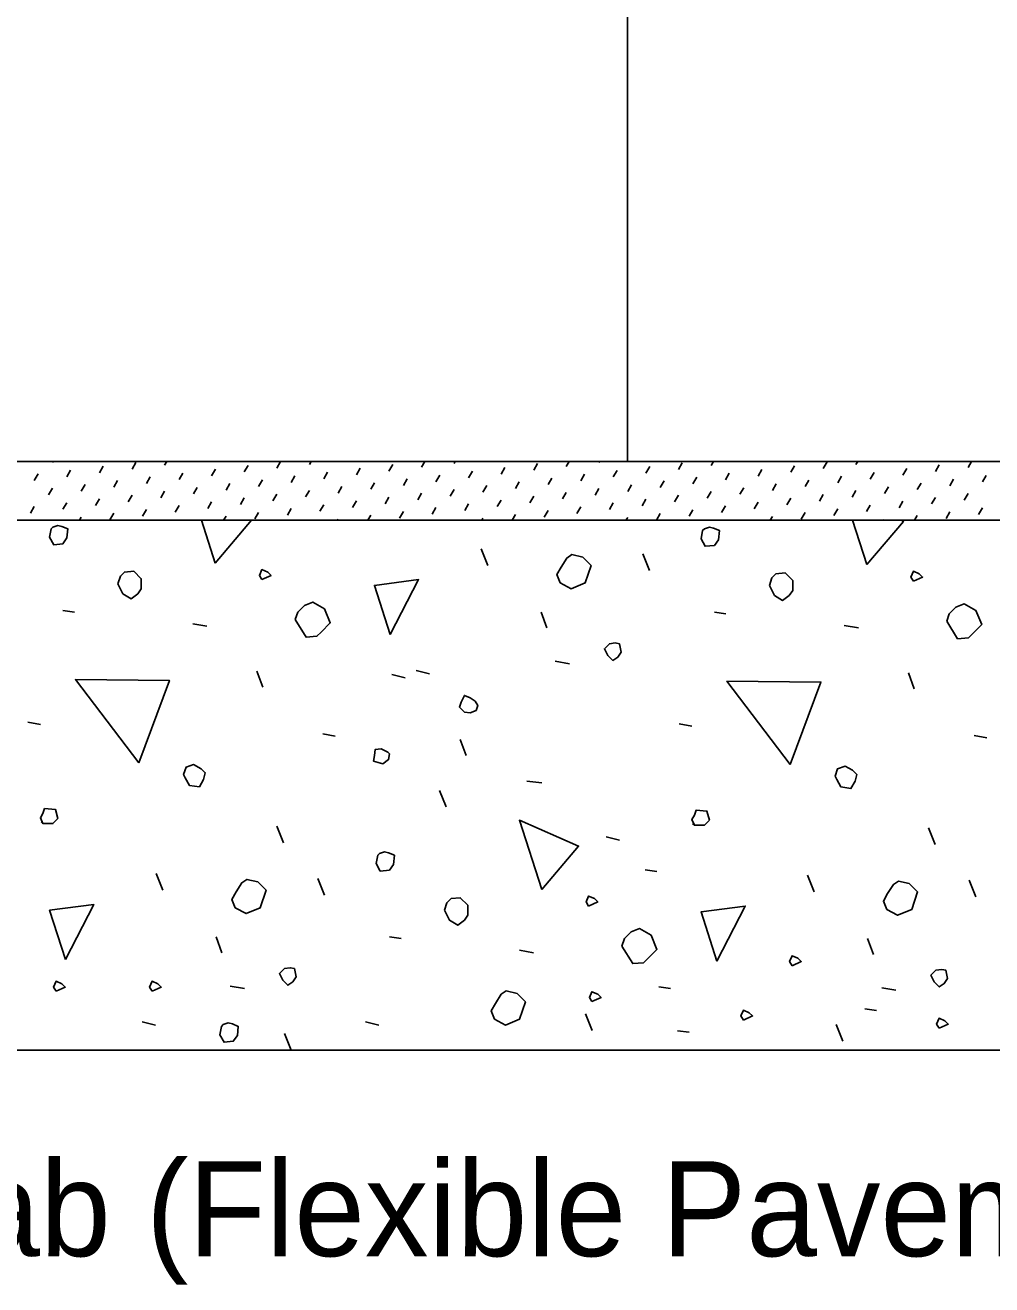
# Model space of a CAD drawing. Extents: x 0.5 to 40.8, y 1 to 25.8.
# Drawn here: x 4.34 to 6.391, y 9.937 to 12.611 of the extents above; entities that cross this region are included whole.
import ezdxf

# ---------------------------------------------------------------- set-up
doc = ezdxf.new("R2010")
doc.units = 0
for name, color, linetype in [('Dimension', 7, 'Continuous'), ('Miscellaneous', 7, 'Continuous'), ('TrafBarrierConc', 7, 'Continuous')]:
    doc.layers.add(name, color=color, linetype=linetype)

msp = doc.modelspace()

# ---------------------------------------------------------------- linework, layer by layer
at = {"layer": 'Miscellaneous'}
for p, q in [((4.3978, 11.6829), (4.3989, 11.6848)), ((4.4283, 11.6524), (4.4364, 11.6664)), ((4.4975, 11.6605), (4.5056, 11.6745)), ((4.5667, 11.6686), (4.5748, 11.6826)), ((4.6358, 11.6767), (4.6405, 11.6848)), ((4.6664, 11.6462), (4.6745, 11.6602)), ((4.7355, 11.6543), (4.7436, 11.6683)), ((4.8047, 11.6624), (4.8128, 11.6764)), ((4.8739, 11.6705), (4.882, 11.6845)), ((4.943, 11.6786), (4.9466, 11.6848)), ((4.9735, 11.6481), (4.9816, 11.6621)), ((5.0427, 11.6562), (5.0508, 11.6702)), ((5.1119, 11.6643), (5.12, 11.6783)), ((5.181, 11.6724), (5.1882, 11.6848)), ((5.2502, 11.6805), (5.2527, 11.6848)), ((5.2807, 11.6499), (5.2888, 11.6639)), ((5.3499, 11.658), (5.358, 11.672)), ((5.4191, 11.6661), (5.4272, 11.6801)), ((5.4882, 11.6742), (5.4943, 11.6848)), ((5.5574, 11.6823), (5.5588, 11.6848)), ((5.5879, 11.6518), (5.596, 11.6658)), ((5.6571, 11.6599), (5.6652, 11.6739)), ((5.7262, 11.668), (5.7343, 11.682)), ((5.7954, 11.6761), (5.8004, 11.6848)), ((5.8259, 11.6456), (5.834, 11.6596)), ((5.8646, 11.6842), (5.8649, 11.6848)), ((5.8951, 11.6537), (5.9032, 11.6677)), ((5.9643, 11.6618), (5.9724, 11.6758)), ((6.0334, 11.6699), (6.0415, 11.6839)), ((6.1026, 11.678), (6.1065, 11.6848)), ((6.1331, 11.6475), (6.1412, 11.6615)), ((6.2023, 11.6556), (6.2104, 11.6696)), ((6.2715, 11.6637), (6.2796, 11.6777)), ((6.3406, 11.6718), (6.3482, 11.6848)), ((4.3592, 11.6443), (4.3673, 11.6583)), ((4.4589, 11.6219), (4.467, 11.6359)), ((4.528, 11.63), (4.5361, 11.644)), ((4.5972, 11.6381), (4.6053, 11.6521)), ((4.7661, 11.6238), (4.7742, 11.6378)), ((4.8352, 11.6319), (4.8433, 11.6459)), ((4.9044, 11.64), (4.9125, 11.654)), ((5.0732, 11.6256), (5.0813, 11.6396)), ((5.1424, 11.6337), (5.1505, 11.6477)), ((5.2116, 11.6418), (5.2197, 11.6558)), ((5.3113, 11.6194), (5.3194, 11.6334)), ((5.3804, 11.6275), (5.3885, 11.6415)), ((5.4496, 11.6356), (5.4577, 11.6496)), ((5.5188, 11.6437), (5.5269, 11.6577)), ((5.6184, 11.6213), (5.6266, 11.6353)), ((5.6876, 11.6294), (5.6957, 11.6434)), ((5.7568, 11.6375), (5.7649, 11.6515)), ((5.9256, 11.6232), (5.9337, 11.6372)), ((5.9948, 11.6313), (6.0029, 11.6453)), ((6.064, 11.6394), (6.0721, 11.6534)), ((6.2328, 11.625), (6.2409, 11.639)), ((6.302, 11.6331), (6.3101, 11.6471)), ((6.3711, 11.6412), (6.3793, 11.6552)), ((4.3897, 11.6138), (4.3978, 11.6278)), ((4.4894, 11.5913), (4.4975, 11.6053)), ((4.5586, 11.5994), (4.5667, 11.6134)), ((4.6277, 11.6076), (4.6358, 11.6215)), ((4.6969, 11.6157), (4.705, 11.6296)), ((4.7966, 11.5932), (4.8047, 11.6072)), ((4.8657, 11.6013), (4.8739, 11.6153)), ((4.9349, 11.6094), (4.943, 11.6234)), ((5.0041, 11.6175), (5.0122, 11.6315)), ((5.1038, 11.5951), (5.1119, 11.6091)), ((5.1729, 11.6032), (5.181, 11.6172)), ((5.2421, 11.6113), (5.2502, 11.6253)), ((5.411, 11.597), (5.4191, 11.611)), ((5.4801, 11.6051), (5.4882, 11.6191)), ((5.5493, 11.6132), (5.5574, 11.6272)), ((5.7181, 11.5989), (5.7262, 11.6129)), ((5.7873, 11.607), (5.7954, 11.621)), ((5.8565, 11.6151), (5.8646, 11.6291)), ((5.9562, 11.5926), (5.9643, 11.6066)), ((6.0253, 11.6007), (6.0334, 11.6147)), ((6.0945, 11.6088), (6.1026, 11.6228)), ((6.1637, 11.6169), (6.1718, 11.6309)), ((6.2634, 11.5945), (6.2715, 11.6085)), ((6.3325, 11.6026), (6.3406, 11.6166)), ((4.3511, 11.5751), (4.3592, 11.5891)), ((4.4202, 11.5832), (4.4283, 11.5972)), ((4.5891, 11.5689), (4.5972, 11.5829)), ((4.6583, 11.577), (4.6664, 11.591)), ((4.7274, 11.5851), (4.7355, 11.5991)), ((4.8963, 11.5708), (4.9044, 11.5848)), ((4.9654, 11.5789), (4.9735, 11.5929)), ((5.0346, 11.587), (5.0427, 11.601)), ((5.1343, 11.5646), (5.1424, 11.5786)), ((5.2035, 11.5727), (5.2116, 11.5867)), ((5.2726, 11.5808), (5.2807, 11.5948)), ((5.3418, 11.5889), (5.3499, 11.6029)), ((5.4415, 11.5665), (5.4496, 11.5804)), ((5.5107, 11.5746), (5.5188, 11.5885)), ((5.5798, 11.5827), (5.5879, 11.5966)), ((5.649, 11.5908), (5.6571, 11.6048)), ((5.7487, 11.5683), (5.7568, 11.5823)), ((5.8178, 11.5764), (5.8259, 11.5904)), ((5.887, 11.5845), (5.8951, 11.5985)), ((6.0559, 11.5702), (6.064, 11.5842)), ((6.125, 11.5783), (6.1331, 11.5923)), ((6.1942, 11.5864), (6.2023, 11.6004)), ((6.363, 11.5721), (6.3711, 11.5861)), ((4.4549, 11.5598), (4.4589, 11.5667)), ((4.5199, 11.5608), (4.528, 11.5748)), ((4.6965, 11.5598), (4.6969, 11.5605)), ((4.761, 11.5598), (4.7661, 11.5686)), ((4.8271, 11.5627), (4.8352, 11.5767)), ((5.0026, 11.5598), (5.0041, 11.5624)), ((5.0671, 11.5598), (5.0732, 11.5705)), ((5.3087, 11.5598), (5.3113, 11.5642)), ((5.3732, 11.5598), (5.3804, 11.5723)), ((5.6148, 11.5598), (5.6184, 11.5661)), ((5.6795, 11.5602), (5.6876, 11.5742)), ((5.8564, 11.5598), (5.8565, 11.5599)), ((5.9209, 11.5598), (5.9256, 11.568)), ((5.9867, 11.5621), (5.9948, 11.5761)), ((6.1625, 11.5598), (6.1637, 11.5618)), ((6.227, 11.5598), (6.2328, 11.5699)), ((6.2939, 11.564), (6.302, 11.578)), ((5.3215, 11.4639), (5.3073, 11.4993)), ((5.6644, 11.4533), (5.6503, 11.4887)), ((4.4199, 11.3685), (4.4446, 11.3649)), ((5.447, 11.3313), (5.4346, 11.3649)), ((5.8023, 11.3649), (5.827, 11.3614)), ((4.6957, 11.3402), (4.7257, 11.3349)), ((6.0781, 11.3366), (6.1081, 11.3313)), ((5.4646, 11.2606), (5.4947, 11.2553)), ((4.8442, 11.2058), (4.8318, 11.2394)), ((5.1182, 11.2324), (5.1465, 11.2253)), ((5.1694, 11.2412), (5.1977, 11.2341)), ((6.2266, 11.2023), (6.2142, 11.2359)), ((4.3457, 11.1316), (4.3722, 11.1263)), ((5.728, 11.1281), (5.7546, 11.1227)), ((4.9714, 11.1068), (4.998, 11.1015)), ((6.3538, 11.1033), (6.3804, 11.098)), ((5.2755, 11.0609), (5.2631, 11.0945)), ((5.4045, 11.0061), (5.4364, 11.0025)), ((5.2331, 10.9513), (5.2189, 10.9866)), ((4.8884, 10.8753), (4.8742, 10.9106)), ((5.5725, 10.8876), (5.6008, 10.8806)), ((6.2707, 10.8717), (6.2566, 10.9071)), ((4.632, 10.7745), (4.6179, 10.8099)), ((5.6553, 10.8177), (5.68, 10.8142)), ((6.0144, 10.771), (6.0003, 10.8063)), ((4.975, 10.7639), (4.9608, 10.7992)), ((6.3574, 10.7604), (6.3432, 10.7957)), ((4.7575, 10.6419), (4.7452, 10.6755)), ((5.1129, 10.6755), (5.1376, 10.672)), ((6.1399, 10.6384), (6.1276, 10.672)), ((5.3886, 10.6472), (5.4187, 10.6419)), ((4.7752, 10.5712), (4.8053, 10.5659)), ((5.6847, 10.5697), (5.7095, 10.5662)), ((6.1576, 10.5677), (6.1877, 10.5624)), ((5.5429, 10.4768), (5.5288, 10.5122)), ((6.1218, 10.523), (6.1466, 10.5195)), ((4.5883, 10.4953), (4.6166, 10.4883)), ((5.0622, 10.4953), (5.0905, 10.4883)), ((6.0749, 10.4543), (6.0608, 10.4896)), ((4.9045, 10.4351), (4.8903, 10.4705)), ((5.724, 10.4764), (5.7488, 10.4729))]:
    msp.add_line(p, q, dxfattribs=at)
for points in [[(4.7434, 11.4692), (4.7139, 11.5598)], [(4.82, 11.5598), (4.7434, 11.4692)], [(6.1258, 11.4657), (6.0952, 11.5598)], [(6.1986, 11.5598), (6.2036, 11.5576), (6.1258, 11.4657)], [(4.3916, 11.524), (4.4005, 11.5081), (4.4199, 11.5099), (4.4287, 11.5223), (4.4305, 11.5417), (4.4181, 11.547), (4.4093, 11.5488), (4.3987, 11.5452), (4.3951, 11.5417), (4.3916, 11.524)], [(5.774, 11.5205), (5.7828, 11.5046), (5.8023, 11.5064), (5.8111, 11.5187), (5.8129, 11.5382), (5.8005, 11.5435), (5.7917, 11.5452), (5.7811, 11.5417), (5.7775, 11.5382), (5.774, 11.5205)], [(5.4753, 11.4268), (5.4982, 11.4144), (5.5283, 11.4268), (5.5407, 11.4639), (5.523, 11.4816), (5.5, 11.4869), (5.4894, 11.4798), (5.477, 11.4604), (5.4682, 11.4445), (5.4753, 11.4268)], [(4.5366, 11.425), (4.5472, 11.4038), (4.5649, 11.3932), (4.579, 11.4038), (4.5861, 11.4144), (4.5861, 11.4356), (4.5702, 11.4516), (4.5507, 11.4498), (4.5419, 11.4409), (4.5366, 11.425)], [(4.8424, 11.4339), (4.8618, 11.4427), (4.8548, 11.4498), (4.8424, 11.4551), (4.8371, 11.4427), (4.8424, 11.4339)], [(5.919, 11.4215), (5.9296, 11.4003), (5.9472, 11.3897), (5.9614, 11.4003), (5.9685, 11.4109), (5.9685, 11.4321), (5.9526, 11.448), (5.9331, 11.4463), (5.9243, 11.4374), (5.919, 11.4215)], [(6.2248, 11.4303), (6.2442, 11.4392), (6.2372, 11.4463), (6.2248, 11.4516), (6.2195, 11.4392), (6.2248, 11.4303)], [(5.1146, 11.3172), (5.081, 11.4215), (5.1747, 11.4339), (5.1146, 11.3172)], [(4.9131, 11.349), (4.9361, 11.3119), (4.9591, 11.3137), (4.9679, 11.3225), (4.9874, 11.342), (4.975, 11.372), (4.9502, 11.3861), (4.9326, 11.3791), (4.9184, 11.3649), (4.9131, 11.349)], [(6.2955, 11.3455), (6.3185, 11.3084), (6.3415, 11.3101), (6.3503, 11.319), (6.3697, 11.3384), (6.3574, 11.3685), (6.3326, 11.3826), (6.3149, 11.3755), (6.3008, 11.3614), (6.2955, 11.3455)], [(5.576, 11.273), (5.5866, 11.2624), (5.5972, 11.2695), (5.6043, 11.2801), (5.6008, 11.2978), (5.5919, 11.2995), (5.5796, 11.2978), (5.5689, 11.2872), (5.576, 11.273)], [(4.5808, 11.045), (4.4464, 11.2217), (4.6462, 11.22), (4.5808, 11.045)], [(5.9632, 11.0414), (5.8288, 11.2182), (6.0286, 11.2164), (5.9632, 11.0414)], [(5.272, 11.1528), (5.2843, 11.151), (5.2967, 11.1563), (5.3002, 11.1669), (5.2949, 11.1758), (5.2843, 11.1829), (5.272, 11.1882), (5.2649, 11.174), (5.2614, 11.1634), (5.272, 11.1528)], [(5.0793, 11.0485), (5.0987, 11.0432), (5.1111, 11.052), (5.1129, 11.0644), (5.1093, 11.0679), (5.0952, 11.075), (5.0828, 11.0733), (5.081, 11.0609), (5.0793, 11.0485)], [(4.6798, 11.0131), (4.6886, 10.9972), (4.7098, 10.9937), (4.7187, 11.0096), (4.7222, 11.0238), (4.7133, 11.0326), (4.6974, 11.0414), (4.6815, 11.0361), (4.6762, 11.0202), (4.6798, 11.0131)], [(6.0622, 11.0096), (6.071, 10.9937), (6.0922, 10.9902), (6.101, 11.0061), (6.1046, 11.0202), (6.0957, 11.0291), (6.0798, 11.0379), (6.0639, 11.0326), (6.0586, 11.0167), (6.0622, 11.0096)], [(4.3775, 10.9159), (4.3987, 10.9159), (4.4093, 10.9265), (4.404, 10.946), (4.381, 10.9477), (4.3775, 10.9371), (4.3722, 10.9283), (4.3775, 10.9159), (4.3739, 10.9195)], [(5.7599, 10.9124), (5.7811, 10.9124), (5.7917, 10.923), (5.7864, 10.9424), (5.7634, 10.9442), (5.7599, 10.9336), (5.7546, 10.9248), (5.7599, 10.9124), (5.7563, 10.9159)], [(5.4364, 10.7763), (5.3886, 10.923), (5.5141, 10.8682), (5.4364, 10.7763)], [(5.0846, 10.8311), (5.0934, 10.8152), (5.1129, 10.8169), (5.1217, 10.8293), (5.1235, 10.8487), (5.1111, 10.854), (5.1023, 10.8558), (5.0916, 10.8523), (5.0881, 10.8487), (5.0846, 10.8311)], [(4.7858, 10.7374), (4.8088, 10.725), (4.8389, 10.7374), (4.8512, 10.7745), (4.8336, 10.7922), (4.8106, 10.7975), (4.8, 10.7904), (4.7876, 10.771), (4.7788, 10.7551), (4.7858, 10.7374)], [(6.1682, 10.7338), (6.1912, 10.7215), (6.2213, 10.7338), (6.2336, 10.771), (6.2159, 10.7886), (6.193, 10.7939), (6.1824, 10.7869), (6.17, 10.7674), (6.1611, 10.7515), (6.1682, 10.7338)], [(5.2295, 10.7321), (5.2401, 10.7109), (5.2578, 10.7003), (5.272, 10.7109), (5.279, 10.7215), (5.279, 10.7427), (5.2631, 10.7586), (5.2437, 10.7568), (5.2348, 10.748), (5.2295, 10.7321)], [(5.5354, 10.7409), (5.5548, 10.7498), (5.5477, 10.7568), (5.5354, 10.7621), (5.5301, 10.7498), (5.5354, 10.7409)], [(4.4252, 10.6278), (4.3916, 10.7321), (4.4853, 10.7444), (4.4252, 10.6278)], [(5.8076, 10.6242), (5.774, 10.7285), (5.8677, 10.7409), (5.8076, 10.6242)], [(5.6061, 10.6561), (5.6291, 10.6189), (5.652, 10.6207), (5.6609, 10.6295), (5.6803, 10.649), (5.6679, 10.679), (5.6432, 10.6932), (5.6255, 10.6861), (5.6114, 10.672), (5.6061, 10.6561)], [(5.9672, 10.6141), (5.9867, 10.623), (5.9796, 10.63), (5.9672, 10.6353), (5.9619, 10.623), (5.9672, 10.6141)], [(4.8866, 10.5836), (4.8972, 10.573), (4.9078, 10.58), (4.9149, 10.5907), (4.9113, 10.6083), (4.9025, 10.6101), (4.8901, 10.6083), (4.8795, 10.5977), (4.8866, 10.5836)], [(6.269, 10.58), (6.2796, 10.5694), (6.2902, 10.5765), (6.2973, 10.5871), (6.2937, 10.6048), (6.2849, 10.6066), (6.2725, 10.6048), (6.2619, 10.5942), (6.269, 10.58)], [(4.4056, 10.5601), (4.425, 10.5689), (4.4179, 10.576), (4.4056, 10.5813), (4.4003, 10.5689), (4.4056, 10.5601)], [(4.6094, 10.5601), (4.6288, 10.5689), (4.6217, 10.576), (4.6094, 10.5813), (4.6041, 10.5689), (4.6094, 10.5601)], [(5.336, 10.5007), (5.359, 10.4884), (5.389, 10.5007), (5.4014, 10.5379), (5.3837, 10.5555), (5.3607, 10.5608), (5.3501, 10.5538), (5.3378, 10.5343), (5.3289, 10.5184), (5.336, 10.5007)], [(5.5424, 10.538), (5.5619, 10.5468), (5.5548, 10.5539), (5.5424, 10.5592), (5.5371, 10.5468), (5.5424, 10.538)], [(5.8641, 10.4987), (5.8835, 10.5076), (5.8765, 10.5146), (5.8641, 10.5199), (5.8588, 10.5076), (5.8641, 10.4987)], [(4.7531, 10.4679), (4.7619, 10.452), (4.7814, 10.4538), (4.7902, 10.4662), (4.792, 10.4856), (4.7796, 10.4909), (4.7708, 10.4927), (4.7602, 10.4892), (4.7566, 10.4856), (4.7531, 10.4679)], [(6.2791, 10.4815), (6.2985, 10.4904), (6.2914, 10.4974), (6.2791, 10.5027), (6.2738, 10.4904), (6.2791, 10.4815)]]:
    msp.add_lwpolyline(points, dxfattribs=at)
at = {"layer": 'TrafBarrierConc'}
for p, q in [((5.6177, 15.1849), (5.6177, 11.6848)), ((0.6166, 11.6848), (8.148, 11.6848)), ((0.6167, 11.5598), (8.148, 11.5598)), ((0.6167, 10.4348), (8.148, 10.4348))]:
    msp.add_line(p, q, dxfattribs=at)

# ---------------------------------------------------------------- texts
at = {"layer": 'Dimension'}
msp.add_text('Approach Slab (Flexible Pavement Approach Slab ', height=0.2016, dxfattribs=at).set_placement((2.7531, 9.9977))

doc.saveas('drawing.dxf')
